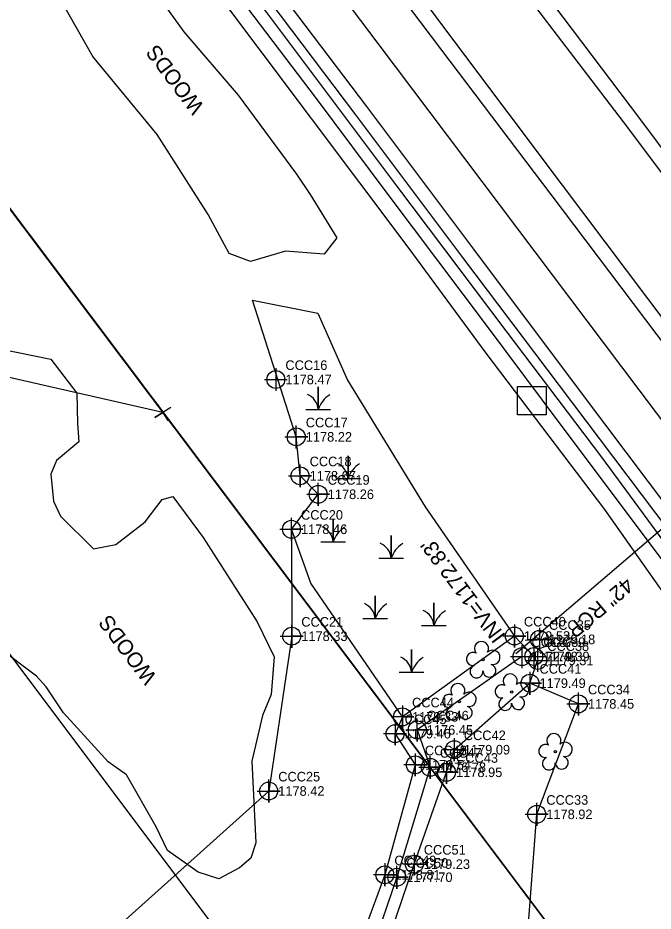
# Model space of a CAD drawing. Extents: x 1262092 to 1264624, y 774970 to 778314.
# Drawn here: x 1262533.2 to 1262699.3, y 777291.5 to 777525 of the extents above; entities that cross this region are included whole.
import ezdxf

# ---------------------------------------------------------------- set-up
doc = ezdxf.new("R2010")
doc.units = 0
for name, color, linetype in [('COGO Default Parcel', 7, 'Continuous'), ('Cogo Default Point CELL', 7, 'Continuous'), ('COGO Default Point Elevation', 7, 'Continuous'), ('COGO Default Point Number', 7, 'Continuous'), ('CTL Secondary Horizontal and Vertical CELL', 7, 'Continuous'), ('Exist Boundary City Limits', 7, 'Continuous'), ('Exist DTM Breakline', 7, 'Continuous'), ('Exist DTM Breakline Cogo Elevation', 7, 'Continuous'), ('Exist DTM Breakline Cogo Number', 7, 'Continuous'), ('Exist DTM Breakline Cogo Point CELL', 7, 'Continuous'), ('Exist DTM Regular Point CELL', 7, 'Continuous'), ('Exist Environmental Wetland Boundary', 7, 'Continuous'), ('Exist Horizontal Alignment', 7, 'Continuous'), ('Exist Horizontal Alignment Tick Small', 7, 'Continuous'), ('Exist Hydro Jurisdictional Stream or Body of Water', 7, 'Continuous'), ('Exist Hydro Stream or Body of Water Cogo Elevation', 7, 'Continuous'), ('Exist Hydro Stream or Body of Water Cogo Number', 7, 'Continuous'), ('Exist Hydro Stream or Body of Water Cogo Point CELL', 7, 'Continuous'), ('Exist Hydro Swamp or Marsh', 7, 'Continuous'), ('Exist Property Corner CELL', 7, 'Continuous'), ('Exist Property Line', 7, 'Continuous'), ('Exist Right of Way Line', 7, 'Continuous'), ('Exist Roads EOP', 7, 'Continuous'), ('Exist Roads EOT', 7, 'Continuous'), ('Exist Structure Minor Pipes RCP 42 Inch', 7, 'Continuous'), ('Exist Structure Minor Pipes RCP 42 Inch Invert', 7, 'Continuous'), ('Exist Structure Minor Pipes RCP 42 Inch Text', 7, 'Continuous'), ('Exist Utilities Telephone UG FO SUE LOS B', 7, 'Continuous'), ('Exist Utilities Water UG Line SUE LOS B', 7, 'Continuous'), ('Exist Vegetation Woods Line Text', 7, 'Continuous'), ('Prop Conc 5in Monolithic Keyed In Island', 7, 'Continuous'), ('Typical Text Label CELL', 7, 'Continuous')]:
    doc.layers.add(name, color=color, linetype=linetype)

# ---------------------------------------------------------------- blocks, each defined once
blk = doc.blocks.new('CTL SECONDARY HORIZONTAL AND VERTICAL')
at = {"layer": 'CTL Secondary Horizontal and Vertical CELL'}
blk.add_line((0, 0), (0, 0), dxfattribs=at)
blk.add_lwpolyline([(-0.1043, 0.0004), (0.0005, 0.1052), (0.1055, 0.0002), (0.0007, -0.1047)], close=True, dxfattribs=at)

msp = doc.modelspace()

# ---------------------------------------------------------------- linework, layer by layer
at = {"layer": 'COGO Default Parcel'}
msp.add_line((1263155.86, 776528.63), (1262121.77, 777902.18), dxfattribs=at)
at = {"layer": 'Cogo Default Point CELL'}
for points in [[(1262665.03, 777361.01), (1262665.03, 777358.01)], [(1262668.13, 777361.05), (1262668.13, 777358.05)], [(1262669.13, 777360), (1262669.13, 777357)], [(1262662.03, 777358.01), (1262665.03, 777358.01)], [(1262665.03, 777358.01), (1262668.03, 777358.01)], [(1262665.03, 777358.01), (1262665.03, 777355.01)], [(1262665.13, 777358.05), (1262668.13, 777358.05)], [(1262666.13, 777357), (1262669.13, 777357)], [(1262668.13, 777358.05), (1262671.13, 777358.05)], [(1262668.13, 777358.05), (1262668.13, 777355.05)], [(1262669.13, 777357), (1262672.13, 777357)], [(1262669.13, 777357), (1262669.13, 777354)]]:
    msp.add_lwpolyline(points, dxfattribs=at)
for centre in [(1262665.03, 777358.01), (1262668.13, 777358.05), (1262669.13, 777357)]:
    msp.add_circle(centre, 2.34, dxfattribs=at)
at = {"layer": 'Exist Boundary City Limits'}
msp.add_line((1263013.39, 776834.66), (1262172.78, 777950.69), dxfattribs=at)
at = {"layer": 'Exist DTM Breakline'}
for points in [[(1262668.13, 777358.05), (1262663.03, 777363.39), (1262633.78, 777342.25), (1262631.85, 777337.86), (1262637.14, 777329.72), (1262629.16, 777300.98), (1262621.57, 777280.42), (1262601.6, 777271.26), (1262584.71, 777248.81)], [(1262592.27, 777246.24), (1262608.93, 777264.97), (1262627.51, 777276.29), (1262636.86, 777303.76), (1262645.3, 777327.77), (1262647.33, 777333.68), (1262667.11, 777351.06), (1262669.13, 777357)]]:
    msp.add_lwpolyline(points, dxfattribs=at)
at = {"layer": 'Exist DTM Breakline Cogo Point CELL'}
for points in [[(1262663.03, 777366.39), (1262663.03, 777360.39), (1262663.03, 777363.39), (1262666.03, 777363.39), (1262660.03, 777363.39)], [(1262667.11, 777354.06), (1262667.11, 777348.06), (1262667.11, 777351.06), (1262670.11, 777351.06), (1262664.11, 777351.06)], [(1262633.78, 777345.25), (1262633.78, 777339.25), (1262633.78, 777342.25), (1262636.78, 777342.25), (1262630.78, 777342.25)], [(1262631.85, 777340.86), (1262631.85, 777334.86), (1262631.85, 777337.86), (1262634.85, 777337.86), (1262628.85, 777337.86)], [(1262647.33, 777336.68), (1262647.33, 777330.68), (1262647.33, 777333.68), (1262650.33, 777333.68), (1262644.33, 777333.68)], [(1262637.14, 777332.72), (1262637.14, 777326.72), (1262637.14, 777329.72), (1262640.14, 777329.72), (1262634.14, 777329.72)], [(1262645.3, 777330.77), (1262645.3, 777324.77), (1262645.3, 777327.77), (1262648.3, 777327.77), (1262642.3, 777327.77)], [(1262636.86, 777306.76), (1262636.86, 777300.76), (1262636.86, 777303.76), (1262639.86, 777303.76), (1262633.86, 777303.76)], [(1262629.16, 777303.98), (1262629.16, 777297.98), (1262629.16, 777300.98), (1262632.16, 777300.98), (1262626.16, 777300.98)]]:
    msp.add_lwpolyline(points, dxfattribs=at)
for centre in [(1262663.03, 777363.39), (1262667.11, 777351.06), (1262633.78, 777342.25), (1262631.85, 777337.86), (1262647.33, 777333.68), (1262637.14, 777329.72), (1262645.3, 777327.77), (1262636.86, 777303.76), (1262629.16, 777300.98)]:
    msp.add_circle(centre, 2.34, dxfattribs=at)
at = {"layer": 'Exist DTM Regular Point CELL'}
for points in [[(1262600.67, 777433.44), (1262600.67, 777430.44)], [(1262597.67, 777430.44), (1262600.67, 777430.44)], [(1262600.67, 777430.44), (1262603.67, 777430.44)], [(1262600.67, 777430.44), (1262600.67, 777427.44)], [(1262603, 777415.45), (1262609, 777415.45), (1262606, 777415.45), (1262606, 777412.45), (1262606, 777418.45)], [(1262604, 777405.27), (1262610, 777405.27), (1262607, 777405.27), (1262607, 777402.27), (1262607, 777408.27)], [(1262608.74, 777400.44), (1262614.74, 777400.44), (1262611.74, 777400.44), (1262611.74, 777397.44), (1262611.74, 777403.44)], [(1262601.75, 777391.3), (1262607.75, 777391.3), (1262604.75, 777391.3), (1262604.75, 777388.3), (1262604.75, 777394.3)], [(1262601.82, 777363.34), (1262607.82, 777363.34), (1262604.82, 777363.34), (1262604.82, 777360.34), (1262604.82, 777366.34)], [(1262669.6, 777365.51), (1262669.6, 777362.51)], [(1262666.6, 777362.51), (1262669.6, 777362.51)], [(1262669.6, 777362.51), (1262672.6, 777362.51)], [(1262669.6, 777362.51), (1262669.6, 777359.51)], [(1262676.78, 777345.65), (1262682.78, 777345.65), (1262679.78, 777345.65), (1262679.78, 777342.65), (1262679.78, 777348.65)], [(1262595.8, 777322.88), (1262601.8, 777322.88), (1262598.8, 777322.88), (1262598.8, 777319.88), (1262598.8, 777325.88)], [(1262665.89, 777316.79), (1262671.89, 777316.79), (1262668.89, 777316.79), (1262668.89, 777313.79), (1262668.89, 777319.79)]]:
    msp.add_lwpolyline(points, dxfattribs=at)
for centre in [(1262600.67, 777430.44), (1262606, 777415.45), (1262607, 777405.27), (1262611.74, 777400.44), (1262604.75, 777391.3), (1262604.82, 777363.34), (1262669.6, 777362.51), (1262679.78, 777345.65), (1262598.8, 777322.88), (1262668.89, 777316.79)]:
    msp.add_circle(centre, 2.34, dxfattribs=at)
at = {"layer": 'Exist Environmental Wetland Boundary'}
msp.add_lwpolyline([(1262663.03, 777363.39), (1262633.78, 777342.25), (1262609.84, 777377.22), (1262604.75, 777391.3), (1262611.74, 777400.44), (1262607, 777405.27), (1262606, 777415.45), (1262594.57, 777451.14), (1262611.61, 777447.76), (1262619.39, 777430.31), (1262639.74, 777397.14), (1262663.03, 777363.39)], dxfattribs=at)
at = {"layer": 'Exist Horizontal Alignment'}
msp.add_line((1264460.35, 775084.79), (1262255.05, 778012.66), dxfattribs=at)
at = {"layer": 'Exist Horizontal Alignment Tick Small'}
for p, q in [((1262654.83, 777357.22), (1262654.83, 777357.22)), ((1262662.34, 777348.75), (1262662.34, 777348.75)), ((1262648.63, 777346.26), (1262648.63, 777346.26)), ((1262673.75, 777333.17), (1262673.75, 777333.17))]:
    msp.add_line(p, q, dxfattribs=at)
for centre in [(1262654.83, 777357.22), (1262662.34, 777348.75), (1262648.63, 777346.26), (1262673.75, 777333.17)]:
    msp.add_circle(centre, 0.326, dxfattribs=at)
for centre, radius, start, end in [((1262654.44, 777360.09), 1.86, 330.1651, 219.7134), ((1262652.22, 777357.37), 1.73, 62.6636, 279.3457), ((1262657.38, 777357.8), 1.9, 257.1011, 134.1999), ((1262656.5, 777354.32), 1.7, 181.2822, 74.56), ((1262653.12, 777354.1), 1.69, 111.5671, 6.231), ((1262661.95, 777351.62), 1.86, 330.1651, 219.7134), ((1262664.89, 777349.34), 1.9, 257.1011, 134.1999), ((1262648.24, 777349.13), 1.86, 330.1651, 219.7134), ((1262659.73, 777348.91), 1.73, 62.6636, 279.3457), ((1262646.02, 777346.41), 1.73, 62.6636, 279.3457), ((1262651.18, 777346.85), 1.9, 257.1011, 134.1999), ((1262660.63, 777345.63), 1.69, 111.5671, 6.231), ((1262664.01, 777345.85), 1.7, 181.2822, 74.56), ((1262646.92, 777343.14), 1.69, 111.5671, 6.231), ((1262650.3, 777343.36), 1.7, 181.2822, 74.56), ((1262673.36, 777336.05), 1.86, 330.1651, 219.7134), ((1262671.14, 777333.33), 1.73, 62.6636, 279.3457), ((1262676.29, 777333.76), 1.9, 257.1011, 134.1999), ((1262672.04, 777330.05), 1.69, 111.5671, 6.231), ((1262675.42, 777330.27), 1.7, 181.2822, 74.56)]:
    msp.add_arc(centre, radius, start, end, dxfattribs=at)
at = {"layer": 'Exist Hydro Jurisdictional Stream or Body of Water'}
msp.add_lwpolyline([(1262665.03, 777358.01), (1262637.64, 777338.85), (1262641.05, 777329.08), (1262632.29, 777300.33), (1262624.53, 777277.63), (1262605.34, 777267.69), (1262588.49, 777247.32)], dxfattribs=at)
at = {"layer": 'Exist Hydro Stream or Body of Water Cogo Point CELL'}
for points in [[(1262634.64, 777338.85), (1262640.64, 777338.85), (1262637.64, 777338.85), (1262637.64, 777335.85), (1262637.64, 777341.85)], [(1262638.05, 777329.08), (1262644.05, 777329.08), (1262641.05, 777329.08), (1262641.05, 777326.08), (1262641.05, 777332.08)], [(1262629.29, 777300.33), (1262635.29, 777300.33), (1262632.29, 777300.33), (1262632.29, 777297.33), (1262632.29, 777303.33)]]:
    msp.add_lwpolyline(points, dxfattribs=at)
for centre in [(1262637.64, 777338.85), (1262641.05, 777329.08), (1262632.29, 777300.33)]:
    msp.add_circle(centre, 2.34, dxfattribs=at)
at = {"layer": 'Exist Hydro Swamp or Marsh'}
for points in [[(1262608.54, 777422.63), (1262611.76, 777422.63), (1262611.76, 777428.55), (1262611.76, 777422.63), (1262614.99, 777422.63)], [(1262616.32, 777404.59), (1262619.54, 777404.59), (1262619.54, 777410.51), (1262619.54, 777404.59), (1262622.77, 777404.59)], [(1262612.42, 777387.99), (1262615.65, 777387.99), (1262615.65, 777393.91), (1262615.65, 777387.99), (1262618.87, 777387.99)], [(1262604.75, 777391.3), (1262604.82, 777363.34), (1262598.8, 777322.88), (1262534.16, 777264.81), (1262547.49, 777244.74), (1262568.12, 777235.16), (1262587.24, 777230.33), (1262613.58, 777225.11), (1262665.73, 777245.42), (1262666.36, 777283.75), (1262668.89, 777316.79), (1262679.78, 777345.65), (1262667.11, 777351.06)], [(1262627.6, 777383.72), (1262630.82, 777383.72), (1262630.82, 777389.63), (1262630.82, 777383.72), (1262634.05, 777383.72)], [(1262623.43, 777367.94), (1262626.65, 777367.94), (1262626.65, 777373.86), (1262626.65, 777367.94), (1262629.88, 777367.94)], [(1262638.76, 777366.17), (1262641.99, 777366.17), (1262641.99, 777372.09), (1262641.99, 777366.17), (1262645.21, 777366.17)], [(1262632.95, 777353.94), (1262636.17, 777353.94), (1262636.17, 777359.85), (1262636.17, 777353.94), (1262639.4, 777353.94)]]:
    msp.add_lwpolyline(points, dxfattribs=at)
for centre, radius, start, end in [((1262607.16, 777422.3), 4.61, 4.1403, 67.535), ((1262618.6, 777420.36), 7.21, 122.1274, 161.6222), ((1262614.94, 777404.26), 4.61, 4.1403, 67.535), ((1262626.39, 777402.32), 7.21, 122.1274, 161.6222), ((1262611.05, 777387.66), 4.61, 4.1403, 67.535), ((1262622.49, 777385.72), 7.21, 122.1274, 161.6222), ((1262626.22, 777383.38), 4.61, 4.1403, 67.535), ((1262637.67, 777381.44), 7.21, 122.1274, 161.6222), ((1262622.05, 777367.61), 4.61, 4.1403, 67.535), ((1262633.49, 777365.67), 7.21, 122.1274, 161.6222), ((1262637.39, 777365.84), 4.61, 4.1403, 67.535), ((1262648.83, 777363.9), 7.21, 122.1274, 161.6222), ((1262631.57, 777353.6), 4.61, 4.1403, 67.535), ((1262643.01, 777351.66), 7.21, 122.1274, 161.6222)]:
    msp.add_arc(centre, radius, start, end, dxfattribs=at)
at = {"layer": 'Exist Property Corner CELL'}
msp.add_line((1262571.14, 777421.81), (1262571.14, 777421.81), dxfattribs=at)
msp.add_lwpolyline([(1262573.25, 777423.14), (1262569.02, 777420.48), (1262571.14, 777421.81), (1262572.47, 777419.7), (1262569.8, 777423.93)], dxfattribs=at)
at = {"layer": 'Exist Property Line'}
msp.add_line((1262571.14, 777421.81), (1262137.51, 777520.55), dxfattribs=at)
at = {"layer": 'Exist Right of Way Line'}
msp.add_line((1262172.78, 777950.69), (1263224.83, 776553.94), dxfattribs=at)
at = {"layer": 'Exist Roads EOP'}
for points in [[(1262982.53, 777073.82), (1262955.55, 777109.3), (1262928.42, 777145.56), (1262900.69, 777182.74), (1262872.34, 777220.82), (1262844.32, 777257.6), (1262815.63, 777295.35), (1262787.99, 777332.27), (1262760.77, 777368.27), (1262732.29, 777406.26), (1262703.53, 777444.22), (1262703.55, 777444.2), (1262675.64, 777481.25), (1262647.24, 777519.05), (1262619.25, 777556.57), (1262590.88, 777594.45), (1262562.41, 777631.96), (1262533.86, 777669.85), (1262506.16, 777706.68)], [(1262930.86, 777089.4), (1262902.71, 777126.43), (1262875.01, 777163.54), (1262846.68, 777201.15), (1262818.83, 777237.2), (1262790.81, 777274.63), (1262762.38, 777312.81), (1262734.99, 777348.79), (1262707.23, 777385.88), (1262678.03, 777424.58), (1262678.1, 777424.6), (1262649.57, 777462.36), (1262621.56, 777499.63), (1262593.49, 777536.82), (1262564.97, 777574.69), (1262536.79, 777612.19), (1262508.59, 777649.5), (1262480.62, 777686.61)], [(1262551.17, 777683.56), (1262580.06, 777645.73), (1262608.84, 777607.53), (1262637.53, 777569.2), (1262664.94, 777532.66), (1262692.64, 777496.32), (1262720.62, 777458.91), (1262748.48, 777421.14), (1262777.36, 777382.85), (1262804.87, 777346.49), (1262832.58, 777309.22), (1262861.34, 777271.61), (1262889.26, 777234.57), (1262918.02, 777196.13), (1262945.71, 777159.53), (1262972.54, 777124.15), (1262999.26, 777088.5)]]:
    msp.add_lwpolyline(points, dxfattribs=at)
at = {"layer": 'Exist Roads EOT'}
for points in [[(1262979.34, 777071.55), (1262952.73, 777106.88), (1262925.27, 777143.52), (1262897.25, 777180.33), (1262868.7, 777218.05), (1262841.03, 777254.71), (1262812.09, 777292.76), (1262784.33, 777329.52), (1262756.93, 777366.26), (1262729.04, 777403.83), (1262700.43, 777442.05), (1262700.42, 777442.08), (1262672.68, 777478.81), (1262644.08, 777516.56), (1262615.98, 777553.77), (1262587.41, 777591.99), (1262558.81, 777629.41), (1262530.21, 777667.14), (1262502.53, 777703.54)], [(1262933.46, 777091.49), (1262905.72, 777128.55), (1262877.63, 777165.57), (1262849.13, 777203), (1262821.64, 777239.58), (1262793.48, 777276.64), (1262765, 777314.68), (1262737.64, 777351.02), (1262709.57, 777388.53), (1262680.86, 777426.61), (1262652.4, 777464.54), (1262624.47, 777501.81), (1262596.33, 777538.99), (1262567.58, 777576.78), (1262539.34, 777614.06), (1262511.28, 777651.42), (1262483.32, 777688.89)], [(1262554.72, 777686.15), (1262583.3, 777648.11), (1262611.88, 777610.15), (1262640.7, 777571.7), (1262668.16, 777535.24), (1262695.77, 777498.64), (1262723.78, 777461.2), (1262751.96, 777423.82), (1262781.01, 777385.34), (1262781, 777385.31), (1262808.32, 777349.17), (1262836.1, 777312), (1262864.5, 777274.02), (1262892.16, 777237.27), (1262921.03, 777198.81), (1262948.88, 777161.95), (1262975.45, 777126.54), (1263002.46, 777090.67)]]:
    msp.add_lwpolyline(points, dxfattribs=at)
at = {"layer": 'Exist Structure Minor Pipes RCP 42 Inch'}
msp.add_line((1262801.86, 777477.16), (1262663.41, 777358.76), dxfattribs=at)
at = {"layer": 'Exist Utilities Telephone UG FO SUE LOS B'}
msp.add_lwpolyline([(1262910.35, 777090.71), (1262890.34, 777118.27), (1262865.78, 777158.05), (1262838.45, 777189.77), (1262811.38, 777217.63), (1262774.04, 777266.39), (1262739.96, 777320.46), (1262735.6, 777333.52), (1262715.57, 777355.48), (1262686.67, 777396.44), (1262655.65, 777437.37), (1262635.3, 777465.04), (1262584.48, 777532.7), (1262553.29, 777574), (1262535.57, 777596.2), (1262497.69, 777644.72), (1262472.81, 777678.82)], dxfattribs=at)
at = {"layer": 'Exist Utilities Water UG Line SUE LOS B'}
msp.add_lwpolyline([(1262961.53, 777041.32), (1262916.91, 777099.45), (1262892.75, 777131.3), (1262862.6, 777171.1), (1262817.98, 777226.85), (1262789.55, 777268.74), (1262774.27, 777287.66), (1262763.83, 777305.05), (1262732.33, 777346.94), (1262685.88, 777410.11), (1262660.87, 777443.18), (1262632.31, 777481.08), (1262598.3, 777526.4), (1262560.14, 777576.52), (1262506.51, 777647.45), (1262479.01, 777683.48), (1262453.07, 777718.25), (1262416.94, 777766.02), (1262382.77, 777811.78), (1262358.61, 777844.73), (1262327.38, 777885.68), (1262302.32, 777918.54), (1262259.45, 777971.43), (1262223.66, 778020.3)], dxfattribs=at)
at = {"layer": 'Prop Conc 5in Monolithic Keyed In Island'}
for points in [[(1262566.24, 777535.78), (1262576.59, 777521.35), (1262590.84, 777504.73), (1262606.08, 777484.13), (1262609.66, 777478.83), (1262616.58, 777467.51), (1262613.32, 777463.24), (1262603.19, 777464.01), (1262594.01, 777461.3), (1262588.48, 777463.42), (1262582.97, 777473.59), (1262569.65, 777494.49), (1262552.77, 777514.91), (1262542.28, 777533.51)], [(1262528.52, 777438.49), (1262541.83, 777435.77), (1262548.67, 777426.89), (1262548.76, 777418.93), (1262549.12, 777414.12), (1262543.35, 777409.28), (1262541.79, 777405.69), (1262542.51, 777398.66), (1262544.36, 777394.71), (1262552.97, 777386.2), (1262558.8, 777387.33), (1262566.49, 777393.27), (1262570.98, 777399.1), (1262573.77, 777399.88), (1262581.68, 777389.14), (1262595.81, 777367.06), (1262600.24, 777357.95), (1262599.46, 777348.08), (1262597.2, 777342.61), (1262594.41, 777330.69), (1262595.47, 777309.37), (1262594.16, 777305.35), (1262591.13, 777302.77), (1262585.73, 777299.91), (1262580.39, 777301.64), (1262572.3, 777307.35), (1262569.34, 777313.48), (1262561.62, 777327.13), (1262556.81, 777330.52), (1262545.13, 777343.3), (1262540.58, 777350.1), (1262538.12, 777352.86), (1262533.52, 777356.32), (1262526.27, 777361.86)]]:
    msp.add_lwpolyline(points, dxfattribs=at)
at = {"layer": 'Typical Text Label CELL'}
msp.add_lwpolyline([(1262768.2, 777292.26), (1262757.43, 777308.58), (1262750.97, 777317.87), (1262727.73, 777348.88), (1262712, 777369.55), (1262697.36, 777389.13), (1262675.04, 777418.88), (1262656.25, 777443.92), (1262630.05, 777478.82), (1262611.34, 777503.87), (1262588.61, 777533.8), (1262569.91, 777558.5), (1262554.82, 777578.68), (1262539.79, 777598.72), (1262516.99, 777628.51), (1262502.14, 777648.38), (1262483.36, 777673.29), (1262468.18, 777693.3), (1262449.46, 777718.32)], dxfattribs=at)

# ---------------------------------------------------------------- block references
at = {"layer": 'CTL Secondary Horizontal and Vertical CELL', "xscale": 50, "yscale": 49.99999999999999, "rotation": 44.99999999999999}
msp.add_blockref('CTL SECONDARY HORIZONTAL AND VERTICAL', (1262667.59, 777424.87), dxfattribs=at)

# ---------------------------------------------------------------- texts
at = {"layer": 'COGO Default Point Elevation'}
for s, p in [('1178.47', (1262603.17, 777429.19)), ('1179.18', (1262672.1, 777361.26)), ('1172.48', (1262667.53, 777356.76)), ('1179.39', (1262670.63, 777356.8)), ('1179.31', (1262671.63, 777355.75))]:
    msp.add_text(s, height=2.5, dxfattribs=at).set_placement(p)
at = {"layer": 'COGO Default Point Number'}
for s, p in [('CCC16', (1262603.17, 777432.94)), ('CCC35', (1262672.1, 777365.01)), ('CCC37', (1262667.53, 777360.51)), ('CCC39', (1262670.63, 777360.55)), ('CCC38', (1262671.63, 777359.5))]:
    msp.add_text(s, height=2.5, dxfattribs=at).set_placement(p)
at = {"layer": 'Exist DTM Breakline Cogo Elevation'}
for s, p in [('1179.53', (1262665.53, 777362.14)), ('1179.49', (1262669.61, 777349.81)), ('1179.33', (1262636.28, 777341)), ('1179.46', (1262634.35, 777336.61)), ('1179.09', (1262649.83, 777332.43)), ('1179.54', (1262639.64, 777328.47)), ('1178.95', (1262647.8, 777326.52)), ('1179.23', (1262639.36, 777302.51)), ('1178.81', (1262631.66, 777299.73))]:
    msp.add_text(s, height=2.5, dxfattribs=at).set_placement(p)
at = {"layer": 'Exist DTM Breakline Cogo Number'}
for s, p in [('CCC40', (1262665.53, 777365.89)), ('CCC41', (1262669.61, 777353.56)), ('CCC44', (1262636.28, 777344.75)), ('CCC45', (1262634.35, 777340.36)), ('CCC42', (1262649.83, 777336.18)), ('CCC48', (1262639.64, 777332.22)), ('CCC43', (1262647.8, 777330.27)), ('CCC51', (1262639.36, 777306.26)), ('CCC49', (1262631.66, 777303.48))]:
    msp.add_text(s, height=2.5, dxfattribs=at).set_placement(p)
at = {"layer": 'Exist Hydro Stream or Body of Water Cogo Elevation'}
for s, p in [('1178.22', (1262608.5, 777414.2)), ('1178.67', (1262609.5, 777404.02)), ('1178.26', (1262614.24, 777399.19)), ('1178.46', (1262607.25, 777390.05)), ('1178.33', (1262607.32, 777362.09)), ('1178.45', (1262682.28, 777344.4)), ('1176.45', (1262640.14, 777337.6)), ('1176.78', (1262643.55, 777327.83)), ('1178.42', (1262601.3, 777321.63)), ('1178.92', (1262671.39, 777315.54)), ('1177.70', (1262634.79, 777299.08))]:
    msp.add_text(s, height=2.5, dxfattribs=at).set_placement(p)
at = {"layer": 'Exist Hydro Stream or Body of Water Cogo Number'}
for s, p in [('CCC17', (1262608.5, 777417.95)), ('CCC18', (1262609.5, 777407.77)), ('CCC19', (1262614.24, 777402.94)), ('CCC20', (1262607.25, 777393.8)), ('CCC21', (1262607.32, 777365.84)), ('CCC34', (1262682.28, 777348.15)), ('CCC46', (1262640.14, 777341.35)), ('CCC47', (1262643.55, 777331.58)), ('CCC25', (1262601.3, 777325.38)), ('CCC33', (1262671.39, 777319.29)), ('CCC50', (1262634.79, 777302.83))]:
    msp.add_text(s, height=2.5, dxfattribs=at).set_placement(p)
at = {"layer": 'Exist Structure Minor Pipes RCP 42 Inch Invert'}
msp.add_text("INV=1172.83'", height=4, rotation=126.9874, dxfattribs=at).set_placement((1262660.91, 777363.51))
at = {"layer": 'Exist Structure Minor Pipes RCP 42 Inch Text'}
msp.add_text('42" RCP', height=4, rotation=220.3627, dxfattribs=at).set_placement((1262692.1, 777378.99))
at = {"layer": 'Exist Vegetation Woods Line Text'}
for p in [(1262582.13, 777501.71), (1262569.73, 777352.68)]:
    msp.add_text('WOODS', height=4, rotation=126.9874, dxfattribs=at).set_placement(p)

doc.saveas('drawing.dxf')
